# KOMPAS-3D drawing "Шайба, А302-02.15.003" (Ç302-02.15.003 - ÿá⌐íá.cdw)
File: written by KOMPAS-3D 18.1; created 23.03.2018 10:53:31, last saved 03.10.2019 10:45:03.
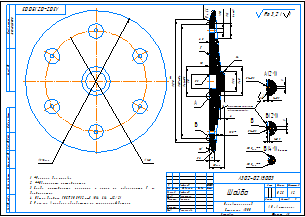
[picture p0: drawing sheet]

Sheet 1: A3, landscape

Document properties: Автор: Милов; Организация: Милов; Полное имя файла: D:\Мембранные насосы\Мембранный электропривод\А302-00.00.000 - ASTRA-302 (МЭ200)\Чертежи ПВХ\А302-02.15.003 - Шайба.cdw; Масса: 0.251914; Параметр неуказанной шероховатости: Ra 3,2

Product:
- Part/product: Шайба  | designation А302-02.15.003
    Материал: Полипропилен  ГОСТ 26996-86 (density 900 kg/m3)
    Масса: 0.251914
    Раздел спецификации: Детали
    Форматы листов документа: A4
- Part/product: Шайба  | designation А302-03.15.003
    Материал: Полипропилен  ГОСТ 26996-86 (density 900 kg/m3)
    Масса: 0.28231
    Раздел спецификации: Детали
    Форматы листов документа: A4
    source file: ..\Чертежи Полипропилен\А302-03.15.003 - Шайба.cdw
- Part/product: Шайба  | designation А302-01.15.003
    Масса: 0.292092
    Раздел спецификации: Детали
    Форматы листов документа: A4
- Part/product: Шайба  | designation А302-03.15.003-01
    Материал: Полипропилен  ГОСТ 26996-86 (density 900 kg/m3)
    Масса: 0.251914
    Раздел спецификации: Детали
    Форматы листов документа: A4
    source file: ..\Чертежи Полипропилен\А302-03.15.003 - Шайба.cdw, А302-02.15.003 - Шайба.cdw

Title block, sheet 1: Наименование: Шайба; designation: А302-02.15.003; Материал: Поливинилхлорид / Стержень  300; Масса: 0,25; scale: 1:2; Количество листов документа: 1; organisation: АО «Астерион»; Форматы листов документа: A3; stored path: \\192.168.87.28\Konstructor_doc\Мембранные насосы\Мембранный электропривод\А302-00.00.000 - ASTRA-302 (МЭ200)\Чертежи\А302-00.15.003 - Шайба.cdw; Разработал: Лифлянд; Проверил: Борисенко; Т. контр.: Лучихин; Утвердил: Григорьева

Views: Вид 1, Местный разрез 1, Спереди, Проекционный вид 2, Выносной элемент 4, Выносной элемент 3, Выносной элемент 5
Referenced files in D:\Мембранные насосы\Мембранный электропривод\А302-00.00.000 - ASTRA-302 (МЭ200)\3Д ПВХ\: А302-01.15.003 - Шайба.m3d
Referenced files in Z:\Мембранные насосы\Мембранный электропривод\А302-00.00.000 - ASTRA-302 (МЭ200)\3Д\: А302-00.15.003 - Шайба.m3d
Referenced files in Z:\Мембранные насосы\Мембранный электропривод\А302-00.00.000 - ASTRA-302 (МЭ200)\3Д ПВХ\: А302-01.15.003 - Шайба.m3d
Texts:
  Ra 1,6
  Зона контакта с мембраной
  поверхность глянцевая
  Ra 0,80
  Ra 3,2
  Ra 3,2 ( )
Dimensions and other numbers on the sheet: 6,5; 40; 28; 4; 6; 20; 3; 10; 13,5; 41±0,3; 157±0,4; 7; 170; 2; 5; 21; 6 отв.; 140; 196; 1±0,1; 0,5; 1:2; 0,25; 03.10.2019

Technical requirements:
  *Размеры для справок.
  **Обеспечить инструментом.
  Следы инструмента, царапины и риски на поверхности Г не
  допускаются.
  Общие допуски ГОСТ 30893.2-mK (H14, h14,  t2/2).
  Размеры в скобках обработать по сопрягаемой детали.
